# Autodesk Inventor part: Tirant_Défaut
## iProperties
Shininess: 64.0
Length Units: 11269
Angle Units: 11279
Time Units: 11290
Mass Units: 11283
Length Display Precision: 3
Angle Display Precision: 2
Compacted: True
Part Number: Tirant_Défaut
Document SubType Name: Modeling
Created: 2006-01
Material: Par défaut
Designer: riri
Density: 0.0
Volumn: 0.0
Area: 0.0
PropertySet Name: Model Information
Control State: 0
Master: False
Checked Out: False
Author: riri
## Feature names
1. Base1
